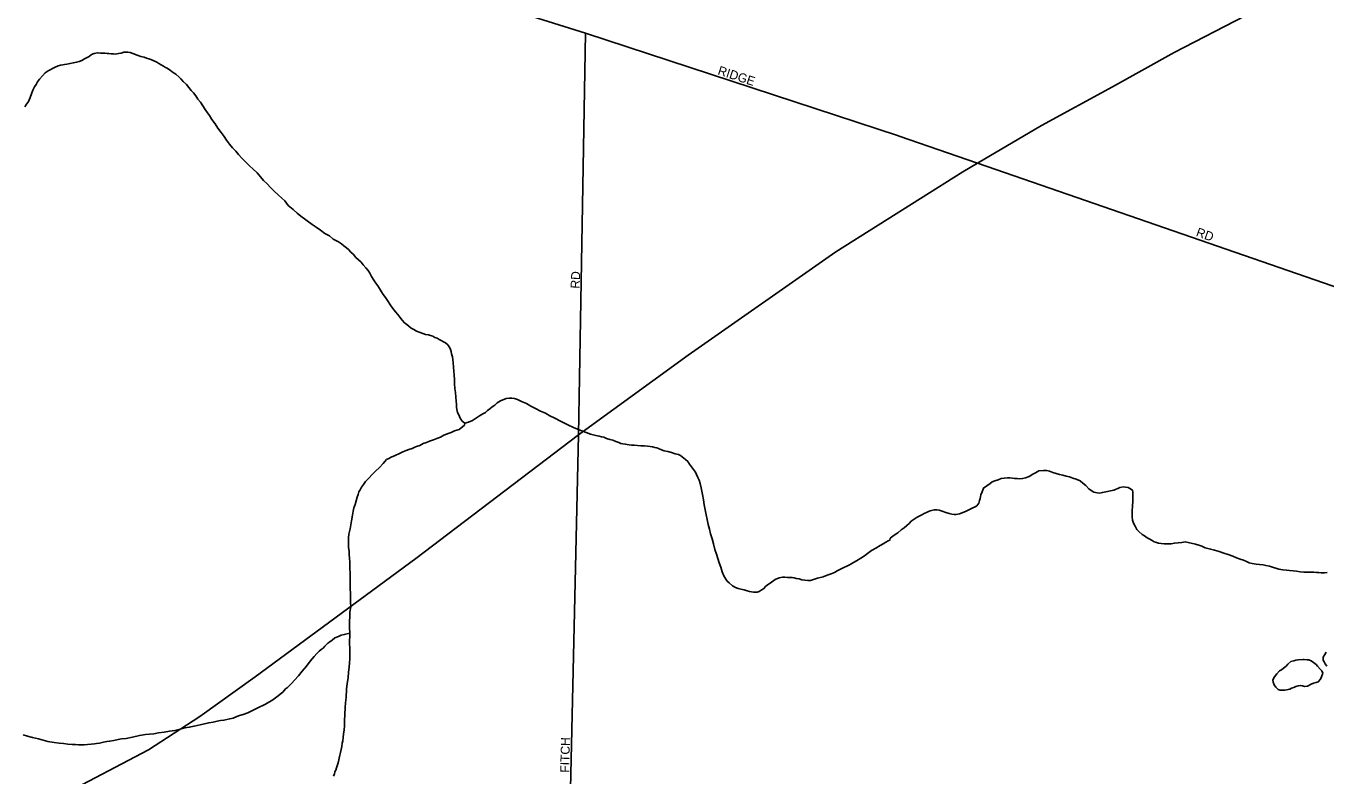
# Model space of a CAD drawing. Extents: x 2010165 to 2382125, y 1060529 to 1407316.
# Drawn here: x 2124358 to 2131582, y 1238984 to 1243150 of the extents above; entities that cross this region are included whole.
import ezdxf

# ---------------------------------------------------------------- set-up
doc = ezdxf.new("R2010")
doc.units = 0
for name, color, linetype in [('GM_X_City_Street', 7, 'Continuous'), ('GM_X_City_Street_Text', 7, 'Continuous'), ('GM_X_Interstate_Route', 7, 'Continuous'), ('GM_X_Minor_Lake', 7, 'Continuous'), ('GM_X_Minor_River', 7, 'Continuous')]:
    doc.layers.add(name, color=color, linetype=linetype)

msp = doc.modelspace()

# ---------------------------------------------------------------- linework, layer by layer
at = {"layer": 'GM_X_City_Street'}
for points in [[(2125355.2, 1243865.2), (2125365.6, 1243794.1), (2125404.1, 1243765.9), (2125870.6, 1243613.3), (2126720.9, 1243346), (2127466.1, 1243110.6), (2129207.1, 1242539.9), (2129210.5, 1242538.7)], [(2127434.2, 1241198.1), (2127466.1, 1243110.6)], [(2129210.5, 1242538.7), (2129645.8, 1242388.3), (2129999, 1242266.2)], [(2129999, 1242266.2), (2131910.9, 1241605.5), (2132179.3, 1241490.7), (2132342.1, 1241405.2), (2132888.2, 1241098.4), (2133124.3, 1240980.2)], [(2127382.1, 1238860.8), (2127383.3, 1238913.2), (2127428.9, 1240879.4), (2127434.2, 1241198.1)]]:
    msp.add_lwpolyline(points, dxfattribs=at)
at = {"layer": 'GM_X_Interstate_Route'}
msp.add_lwpolyline([(2121145.4, 1237792.8), (2121310.9, 1237856), (2121575.6, 1237957.2), (2122073.3, 1238114.8), (2122380.2, 1238196.2), (2122621.1, 1238260), (2123509.8, 1238495.6), (2123792.7, 1238586.2), (2124101.8, 1238685.3), (2124559.1, 1238876.8), (2125038.8, 1239130), (2125324, 1239314), (2125630.5, 1239535.2), (2126524.3, 1240193.1), (2127428.9, 1240879.4), (2128036.8, 1241322.4), (2128857.9, 1241896), (2129564.2, 1242340.4), (2129645.8, 1242388.3), (2130001.7, 1242596.9), (2130394.6, 1242812.1), (2130737.7, 1243003.8), (2131133.3, 1243206.8)], dxfattribs=at)
at = {"layer": 'GM_X_Minor_Lake'}
for points in [[(2131582.8, 1239672.4), (2131574.9, 1239658.4), (2131566.9, 1239644.3), (2131566.9, 1239628.2), (2131571, 1239618.2), (2131577, 1239606.2), (2131587.1, 1239594.2)], [(2131454.9, 1239631.9), (2131426.5, 1239629.8), (2131414.4, 1239627.7), (2131402.4, 1239623.7), (2131386.4, 1239619.6), (2131370.4, 1239605.5), (2131360.4, 1239593.5), (2131346.4, 1239583.4), (2131334.4, 1239573.3), (2131324.3, 1239567.3), (2131308.3, 1239551.2), (2131296.4, 1239535.1), (2131286.4, 1239519), (2131288.4, 1239504.9), (2131294.5, 1239490.9), (2131302.6, 1239476.9), (2131316.7, 1239464.9), (2131326.7, 1239460.9), (2131342.8, 1239461), (2131352.8, 1239461), (2131380.9, 1239467.1), (2131390.9, 1239471.1), (2131402.9, 1239475.2), (2131414.9, 1239481.3), (2131427, 1239485.3), (2131439, 1239487.4), (2131451, 1239485.4), (2131463.1, 1239481.4), (2131479.1, 1239483.5), (2131499.2, 1239493.6), (2131513.2, 1239499.6), (2131527.2, 1239503.7), (2131539.3, 1239507.7), (2131551.3, 1239521.8), (2131557.2, 1239533.9), (2131565.2, 1239556)], [(2131565.2, 1239556), (2131559.1, 1239568), (2131549.1, 1239578), (2131534.9, 1239594), (2131526.9, 1239604), (2131512.8, 1239614), (2131498.7, 1239624), (2131486.7, 1239630), (2131476.6, 1239629.9), (2131460.6, 1239631.9), (2131454.9, 1239631.9)]]:
    msp.add_lwpolyline(points, dxfattribs=at)
at = {"layer": 'GM_X_Minor_River'}
for points in [[(2124682.6, 1242967.5), (2124694.6, 1242973.6), (2124708.6, 1242981.6), (2124722.6, 1242991.7), (2124736.6, 1242997.8), (2124746.7, 1242999.8), (2124756.7, 1243001.8), (2124772.7, 1242999.9), (2124784.8, 1242999.9), (2124796.8, 1243000), (2124808.9, 1242998), (2124818.9, 1242998), (2124830.9, 1242996.1), (2124843, 1242996.1), (2124853, 1242994.1), (2124863.1, 1242996.2), (2124873.1, 1242998.2), (2124887.1, 1243000.2), (2124901.2, 1243004.3), (2124913.2, 1243004.3), (2124923.2, 1243004.4), (2124937.3, 1243002.4), (2124951.3, 1242998.4), (2124975.5, 1242988.5), (2124995.6, 1242980.5), (2125013.6, 1242976.6), (2125027.7, 1242972.6), (2125039.7, 1242968.6), (2125051.8, 1242964.6), (2125063.9, 1242958.7), (2125084, 1242948.7), (2125096, 1242942.7), (2125122.2, 1242926.8), (2125132.2, 1242920.8), (2125142.3, 1242916.8), (2125160.4, 1242902.8), (2125170.4, 1242896.8), (2125180.5, 1242888.8), (2125190.5, 1242882.8), (2125208.7, 1242866.8), (2125218.7, 1242856.8), (2125230.8, 1242842.8), (2125248.9, 1242824.8), (2125263, 1242808.8), (2125275.1, 1242792.8), (2125289.2, 1242778.8), (2125301.3, 1242762.8), (2125313.4, 1242744.8), (2125327.5, 1242726.8), (2125339.6, 1242706.7), (2125353.8, 1242686.7), (2125365.9, 1242668.7), (2125378, 1242652.7), (2125390.1, 1242630.6), (2125408.2, 1242606.6), (2125424.4, 1242582.6), (2125442.5, 1242558.6), (2125458.6, 1242536.5), (2125472.8, 1242516.5), (2125488.9, 1242494.5), (2125505, 1242474.5), (2125523.1, 1242454.5), (2125539.2, 1242436.4), (2125557.4, 1242416.4), (2125575.5, 1242398.4), (2125599.7, 1242374.4), (2125619.8, 1242354.4), (2125641.9, 1242334.4), (2125660.1, 1242312.4), (2125678.2, 1242292.4), (2125698.3, 1242274.4), (2125716.5, 1242252.4), (2125736.6, 1242232.4), (2125758.7, 1242212.4), (2125778.9, 1242194.4), (2125797, 1242178.4), (2125815.1, 1242152.4), (2125843.3, 1242130.4), (2125865.5, 1242110.4), (2125885.6, 1242094.4), (2125947.9, 1242048.5), (2125970.1, 1242032.5), (2125994.2, 1242016.5), (2126018.4, 1241998.5), (2126044.5, 1241984.6), (2126064.6, 1241966.6), (2126094.8, 1241950.6), (2126110.9, 1241940.6), (2126124.9, 1241928.6), (2126139, 1241918.6), (2126149.1, 1241908.6), (2126163.2, 1241894.6), (2126177.3, 1241880.6), (2126191.4, 1241864.6), (2126205.5, 1241850.6), (2126219.6, 1241838.6), (2126231.7, 1241824.6), (2126245.8, 1241806.6), (2126259.9, 1241792.6), (2126267.9, 1241776.6), (2126278, 1241758.6)], [(2124350.4, 1242701.5), (2124360.4, 1242715.6), (2124368.3, 1242725.7), (2124374.3, 1242735.7), (2124380.3, 1242753.8), (2124388.2, 1242773.9), (2124396.2, 1242794), (2124404.2, 1242812.1), (2124414.2, 1242826.2), (2124422.1, 1242840.2), (2124432.1, 1242854.3), (2124450.1, 1242874.4), (2124464.1, 1242890.5), (2124480.1, 1242900.6), (2124516.2, 1242920.8), (2124536.2, 1242928.9), (2124550.2, 1242932.9), (2124562.3, 1242935), (2124572.3, 1242937), (2124584.3, 1242939.1), (2124602.4, 1242943.1), (2124620.4, 1242945.2), (2124638.5, 1242949.3), (2124652.5, 1242953.3), (2124668.5, 1242959.4), (2124682.6, 1242967.5)], [(2126278, 1241758.6), (2126290.2, 1241738.5), (2126302.2, 1241722.5), (2126312.3, 1241706.5), (2126322.4, 1241692.5), (2126332.5, 1241674.4), (2126342.6, 1241658.4), (2126354.7, 1241642.4), (2126366.8, 1241626.4), (2126382.9, 1241600.4), (2126397, 1241580.3), (2126411.2, 1241562.3), (2126423.2, 1241548.3), (2126435.4, 1241532.3), (2126447.4, 1241516.3), (2126461.5, 1241502.3), (2126473.6, 1241492.3), (2126485.7, 1241482.3), (2126497.8, 1241472.3), (2126513.8, 1241464.3), (2126527.9, 1241454.3), (2126548, 1241448.4), (2126562.1, 1241442.4), (2126578.2, 1241436.4), (2126594.2, 1241434.5), (2126606.3, 1241430.5), (2126618.3, 1241426.5), (2126630.4, 1241420.6), (2126642.4, 1241416.6), (2126654.5, 1241408.6), (2126688.7, 1241390.6), (2126702.8, 1241378.6), (2126712.9, 1241362.6), (2126716.9, 1241352.6), (2126721, 1241342.6), (2126723, 1241328.5), (2126727.1, 1241312.5), (2126729.1, 1241296.5), (2126731.2, 1241280.4), (2126733.3, 1241254.3), (2126735.4, 1241232.3), (2126737.5, 1241210.2), (2126739.6, 1241186.1), (2126739.6, 1241162), (2126741.7, 1241136), (2126743.8, 1241113.9), (2126745.9, 1241087.8), (2126748, 1241065.8), (2126750.1, 1241047.7), (2126750.1, 1241033.6), (2126752.2, 1241019.6), (2126756.2, 1241003.6), (2126762.3, 1240989.5), (2126770.4, 1240971.5), (2126782.5, 1240955.5), (2126796.6, 1240943.5), (2126816.6, 1240949.6), (2126838.7, 1240959.7), (2126860.7, 1240973.8), (2126878.7, 1240983.9), (2126896.7, 1240996), (2126910.7, 1241004.1), (2126922.8, 1241014.1), (2126934.8, 1241024.2), (2126948.8, 1241034.3), (2126962.8, 1241044.4), (2126976.8, 1241056.4), (2126994.8, 1241068.6), (2127026.9, 1241080.7), (2127042.9, 1241082.8), (2127057, 1241082.8), (2127073, 1241080.8), (2127089.1, 1241074.9), (2127111.2, 1241064.9), (2127139.3, 1241052.9), (2127163.5, 1241039), (2127189.6, 1241025), (2127217.7, 1241011.1), (2127243.9, 1240999.1), (2127268, 1240985.1), (2127296.1, 1240971.2), (2127328.3, 1240955.2), (2127364.5, 1240937.3), (2127404.7, 1240917.3), (2127446.9, 1240901.4), (2127495.1, 1240883.5), (2127525.2, 1240875.6), (2127543.3, 1240871.6), (2127555.4, 1240867.7), (2127569.4, 1240865.7), (2127583.5, 1240859.7), (2127601.6, 1240853.8), (2127619.6, 1240849.8), (2127635.7, 1240841.8), (2127651.8, 1240835.9), (2127663.9, 1240831.9), (2127673.9, 1240829.9), (2127687.9, 1240827.9), (2127698, 1240826), (2127710, 1240824), (2127722.1, 1240822)], [(2126796.6, 1240943.5), (2126794.6, 1240933.5), (2126764.6, 1240909.3), (2126738.5, 1240901.2), (2126720.5, 1240893.1), (2126708.5, 1240889), (2126694.4, 1240883), (2126680.4, 1240876.9), (2126660.4, 1240866.8), (2126640.4, 1240858.7), (2126622.3, 1240850.6), (2126600.3, 1240844.5), (2126584.2, 1240836.5), (2126564.2, 1240830.4), (2126546.2, 1240820.3), (2126528.1, 1240814.2), (2126518.1, 1240810.2), (2126504.1, 1240804.1), (2126486.1, 1240798), (2126470, 1240792), (2126452, 1240783.9), (2126434, 1240775.8), (2126409.9, 1240763.7), (2126387.9, 1240755.6), (2126373.9, 1240747.5), (2126361.8, 1240741.4), (2126341.8, 1240719.3), (2126321.9, 1240697.2), (2126299.9, 1240677), (2126243.9, 1240620.7), (2126233.9, 1240602.6), (2126221.9, 1240588.5), (2126213.9, 1240574.4), (2126207.9, 1240562.4), (2126204, 1240548.3), (2126198, 1240532.2), (2126192.1, 1240512.1), (2126186.1, 1240492.1), (2126180.2, 1240474), (2126176.2, 1240455.9), (2126172.3, 1240433.8), (2126166.4, 1240401.7), (2126158.5, 1240357.5), (2126152.6, 1240327.4), (2126150.6, 1240307.3), (2126150.7, 1240287.3), (2126150.8, 1240269.2), (2126150.8, 1240253.2), (2126152.9, 1240233.1), (2126153, 1240213), (2126155, 1240195), (2126157.1, 1240170.9), (2126157.2, 1240142.8), (2126159.4, 1240104.7), (2126159.5, 1240074.6), (2126159.6, 1240048.5), (2126159.6, 1240024.4), (2126161.7, 1240000.4), (2126161.8, 1239976.3), (2126161.9, 1239950.2), (2126162, 1239924.1), (2126158.1, 1239894), (2126158.2, 1239867.9), (2126156.2, 1239843.8), (2126156.3, 1239815.7), (2126156.5, 1239769.6), (2126154.6, 1239725.4), (2126156.8, 1239689.3), (2126156.9, 1239661.2), (2126157, 1239635.1), (2126155, 1239613.1), (2126153.1, 1239589), (2126149.2, 1239560.9), (2126147.3, 1239528.7), (2126143.4, 1239498.6), (2126139.5, 1239466.5), (2126137.6, 1239420.3), (2126133.7, 1239390.2), (2126131.8, 1239364.1), (2126128.1, 1239287.9), (2126128.1, 1239263.8), (2126126.2, 1239237.7), (2126122.3, 1239217.6), (2126120.3, 1239197.6), (2126118.4, 1239179.5), (2126114.4, 1239165.4), (2126112.5, 1239147.4), (2126108.5, 1239131.3), (2126104.6, 1239115.2), (2126102.6, 1239099.2), (2126098.7, 1239083.1), (2126094.7, 1239065), (2126090.8, 1239051), (2126086.8, 1239040.9), (2126082.8, 1239028.9), (2126078.8, 1239016.8), (2126074.9, 1239006.8), (2126072.9, 1238996.8), (2126066.9, 1238982.7)], [(2127722.1, 1240822), (2127738.1, 1240822.1), (2127756.2, 1240820.1), (2127774.3, 1240818.2), (2127794.3, 1240818.2), (2127812.4, 1240816.3), (2127826.4, 1240814.3), (2127838.5, 1240812.4), (2127852.6, 1240808.4), (2127862.6, 1240806.4), (2127872.6, 1240802.4), (2127888.7, 1240796.5), (2127904.8, 1240790.5), (2127924.9, 1240786.6), (2127945, 1240780.6), (2127965.1, 1240774.6), (2127983.1, 1240770.7), (2127995.2, 1240764.7), (2128023.3, 1240742.7), (2128035.4, 1240730.7), (2128045.5, 1240716.7), (2128055.6, 1240700.7), (2128067.7, 1240686.7), (2128077.8, 1240672.7), (2128083.8, 1240658.6), (2128091.9, 1240642.6), (2128098, 1240626.6), (2128104.1, 1240608.5), (2128110.2, 1240584.5), (2128116.3, 1240548.4), (2128122.5, 1240518.3), (2128126.6, 1240490.2), (2128132.7, 1240462.1), (2128136.8, 1240434.1), (2128142.9, 1240408), (2128149, 1240381.9), (2128155.1, 1240355.9), (2128161.2, 1240329.8), (2128171.4, 1240301.7), (2128177.5, 1240273.7), (2128185.6, 1240241.6), (2128195.7, 1240215.5), (2128201.8, 1240191.5), (2128210, 1240167.4), (2128218.1, 1240143.3), (2128226.2, 1240117.3), (2128236.3, 1240095.3), (2128246.4, 1240077.2), (2128254.4, 1240067.2), (2128264.5, 1240057.2), (2128284.6, 1240041.2), (2128300.7, 1240031.2), (2128314.8, 1240025.3), (2128330.9, 1240021.3), (2128348.9, 1240017.3), (2128365, 1240013.4), (2128379.1, 1240009.4), (2128389.1, 1240007.4), (2128401.1, 1240005.5), (2128411.2, 1240005.5), (2128421.2, 1240005.5), (2128431.2, 1240009.6), (2128443.2, 1240015.6), (2128455.3, 1240023.7), (2128469.3, 1240037.8), (2128483.3, 1240049.9), (2128493.3, 1240055.9), (2128521.3, 1240076.1), (2128543.3, 1240084.2), (2128561.4, 1240088.3), (2128575.4, 1240088.3), (2128589.5, 1240086.3), (2128603.5, 1240086.4), (2128615.6, 1240086.4), (2128625.6, 1240084.4), (2128637.7, 1240080.5), (2128653.7, 1240078.5), (2128669.8, 1240074.6), (2128685.9, 1240072.6), (2128701.9, 1240070.6), (2128718, 1240070.7), (2128734, 1240074.8), (2128756.1, 1240082.9), (2128788.1, 1240091), (2128810.2, 1240099.1), (2128832.2, 1240107.2), (2128850.3, 1240115.3), (2128866.3, 1240123.3), (2128884.3, 1240133.4), (2128902.3, 1240141.5), (2128918.4, 1240149.6), (2128938.4, 1240159.7), (2128956.4, 1240169.8), (2128972.4, 1240179.9), (2128996.5, 1240194), (2129016.5, 1240206.1), (2129034.5, 1240220.2), (2129056.5, 1240236.3), (2129080.6, 1240250.4), (2129104.6, 1240264.6), (2129120.6, 1240274.6)], [(2129120.6, 1240274.6), (2129136.6, 1240282.7), (2129148.6, 1240290.8), (2129158.7, 1240294.8), (2129160.6, 1240304.9), (2129182.7, 1240321), (2129202.7, 1240335.1), (2129220.7, 1240351.2), (2129238.7, 1240363.3), (2129252.7, 1240375.4), (2129264.7, 1240387.5), (2129276.7, 1240399.6), (2129310.7, 1240421.7), (2129320.7, 1240427.8), (2129332.8, 1240433.8), (2129352.8, 1240443.9), (2129362.8, 1240448), (2129372.8, 1240454), (2129382.8, 1240456.1), (2129404.9, 1240462.2), (2129418.9, 1240462.2), (2129433, 1240460.2), (2129449.1, 1240454.3), (2129469.2, 1240448.3), (2129487.2, 1240442.4), (2129503.3, 1240438.4), (2129515.4, 1240436.4), (2129525.4, 1240436.5), (2129535.4, 1240438.5), (2129545.4, 1240440.5), (2129559.5, 1240446.6), (2129581.5, 1240454.7), (2129601.5, 1240464.8), (2129619.6, 1240472.9), (2129631.6, 1240478.9), (2129641.6, 1240485), (2129653.6, 1240499.1), (2129655.6, 1240515.1), (2129659.5, 1240525.2), (2129661.5, 1240535.2), (2129663.5, 1240545.3), (2129671.4, 1240563.3), (2129679.4, 1240583.4), (2129697.4, 1240595.5), (2129715.4, 1240609.6), (2129727.4, 1240617.7), (2129741.5, 1240623.8), (2129759.5, 1240629.8), (2129777.5, 1240635.9), (2129793.6, 1240638), (2129811.6, 1240640), (2129825.7, 1240640.1), (2129839.7, 1240638.1), (2129851.8, 1240636.2), (2129865.8, 1240636.2), (2129879.9, 1240634.2), (2129895.9, 1240636.3), (2129912, 1240640.4), (2129932, 1240648.5), (2129952, 1240660.6), (2129968.1, 1240668.6), (2129986.1, 1240678.7), (2130012.2, 1240680.8), (2130030.2, 1240680.9), (2130046.3, 1240676.9), (2130064.4, 1240670.9), (2130082.5, 1240665), (2130100.5, 1240659), (2130118.6, 1240655.1), (2130138.7, 1240649.1), (2130156.8, 1240645.1), (2130174.8, 1240639.2), (2130192.9, 1240633.2), (2130215, 1240623.3), (2130231.1, 1240611.3), (2130247.2, 1240597.3), (2130263.4, 1240579.3), (2130277.4, 1240569.3), (2130291.5, 1240561.3), (2130309.6, 1240557.3), (2130325.6, 1240555.4), (2130339.7, 1240559.4), (2130403.8, 1240571.7), (2130415.9, 1240577.8), (2130425.9, 1240581.8), (2130435.9, 1240585.8), (2130455.9, 1240589.9), (2130468, 1240587.9), (2130482.1, 1240586), (2130492.1, 1240582), (2130506.2, 1240572), (2130508.2, 1240560), (2130508.3, 1240549.9), (2130508.3, 1240537.9), (2130508.4, 1240519.8), (2130508.4, 1240503.8), (2130506.5, 1240489.7), (2130506.5, 1240475.7), (2130504.5, 1240463.6), (2130504.6, 1240451.6), (2130504.6, 1240439.6)], [(2130504.6, 1240439.6), (2130504.7, 1240423.5), (2130506.8, 1240405.5), (2130512.8, 1240389.4), (2130520.9, 1240371.4), (2130531, 1240353.4), (2130541.1, 1240341.3), (2130561.2, 1240325.4), (2130573.3, 1240317.4), (2130587.4, 1240307.4), (2130599.4, 1240301.4), (2130615.5, 1240291.4), (2130627.6, 1240285.4), (2130639.6, 1240281.5), (2130651.7, 1240277.5), (2130665.7, 1240275.5), (2130681.8, 1240273.6), (2130699.8, 1240273.6), (2130721.9, 1240273.7), (2130740, 1240277.8), (2130760, 1240279.8), (2130780.1, 1240281.9), (2130800.1, 1240284), (2130856.4, 1240272.1), (2130874.5, 1240266.2), (2130892.5, 1240260.2), (2130910.6, 1240252.2), (2130940.7, 1240244.3), (2130962.8, 1240238.3), (2130989, 1240230.4), (2131015.1, 1240222.5), (2131039.2, 1240214.5), (2131063.3, 1240204.6), (2131085.4, 1240196.6), (2131105.5, 1240188.6), (2131123.6, 1240182.7), (2131139.6, 1240174.7), (2131155.7, 1240168.7), (2131171.8, 1240164.8), (2131193.9, 1240160.8), (2131211.9, 1240158.9), (2131232, 1240156.9), (2131248.1, 1240153), (2131268.2, 1240149), (2131290.2, 1240143.1), (2131308.3, 1240137.1), (2131320.4, 1240133.1), (2131330.4, 1240131.1), (2131342.5, 1240129.2), (2131362.5, 1240127.2), (2131378.6, 1240125.3), (2131398.7, 1240123.3), (2131418.7, 1240121.4), (2131438.8, 1240117.4), (2131458.9, 1240115.5), (2131479, 1240115.6), (2131499, 1240115.6), (2131515.1, 1240115.7), (2131529.1, 1240113.7), (2131541.2, 1240113.8), (2131555.2, 1240111.8), (2131573.3, 1240111.8), (2131589.3, 1240113.9)], [(2126156.5, 1239778.1), (2126126.4, 1239769.5), (2126108.4, 1239765.4), (2126094.3, 1239759.3), (2126074.3, 1239751.2), (2126058.3, 1239739.2), (2126046.3, 1239729.1), (2126034.3, 1239721), (2126018.3, 1239704.9), (2126008.3, 1239694.8), (2125998.3, 1239686.8), (2125986.2, 1239676.7), (2125974.3, 1239664.6), (2125958.3, 1239648.5), (2125936.3, 1239622.4), (2125916.3, 1239594.2), (2125892.3, 1239566.1), (2125872.3, 1239539.9), (2125850.4, 1239515.8), (2125834.4, 1239499.6), (2125810.4, 1239475.5), (2125800.4, 1239467.4), (2125784.4, 1239449.3), (2125770.4, 1239439.2), (2125758.3, 1239429.2), (2125730.3, 1239407), (2125688.3, 1239382.8), (2125642.2, 1239360.6), (2125590.1, 1239334.3), (2125564.1, 1239326.2), (2125544, 1239320.1), (2125530, 1239314.1), (2125509.9, 1239306), (2125489.9, 1239301.9), (2125473.9, 1239297.8), (2125457.8, 1239293.8), (2125437.8, 1239291.7), (2125419.7, 1239287.6), (2125397.7, 1239283.5), (2125373.6, 1239279.4), (2125349.5, 1239273.4), (2125325.5, 1239267.3), (2125291.4, 1239261.1), (2125265.3, 1239255), (2125241.2, 1239250.9), (2125215.2, 1239244.8), (2125185.1, 1239236.7), (2125155, 1239232.6), (2125124.9, 1239226.5), (2125094.8, 1239224.4), (2125068.8, 1239218.3), (2125044.7, 1239216.2), (2125022.6, 1239214.1), (2124988.6, 1239208), (2124950.5, 1239199.8), (2124914.4, 1239191.7), (2124888.3, 1239189.6), (2124870.2, 1239187.5), (2124846.2, 1239181.4), (2124822.1, 1239177.3), (2124806.1, 1239175.3), (2124788, 1239171.2), (2124766, 1239167.1), (2124749.9, 1239165.1), (2124737.9, 1239163), (2124681.7, 1239156.8), (2124665.7, 1239156.8), (2124649.6, 1239156.7), (2124633.5, 1239158.7), (2124613.5, 1239158.6), (2124589.4, 1239160.6), (2124565.3, 1239164.5), (2124541.2, 1239166.4), (2124515.1, 1239170.3), (2124479, 1239176.2), (2124452.9, 1239182.2), (2124426.7, 1239190.1), (2124394.6, 1239198.1), (2124366.5, 1239206), (2124342.4, 1239211.9)]]:
    msp.add_lwpolyline(points, dxfattribs=at)

# ---------------------------------------------------------------- texts
at = {"layer": 'GM_X_City_Street_Text'}
for s, rotation, p in [('RIDGE', 341.91368, (2128198.1, 1242882.5)), ('RD', 340.5566, (2130855.9, 1241984.8)), ('RD', 86.98328, (2127433.3, 1241690.5)), ('FITCH', 88.56871, (2127376.1, 1239001.8))]:
    msp.add_text(s, height=50, rotation=rotation, dxfattribs=at).set_placement(p)

doc.saveas('drawing.dxf')
